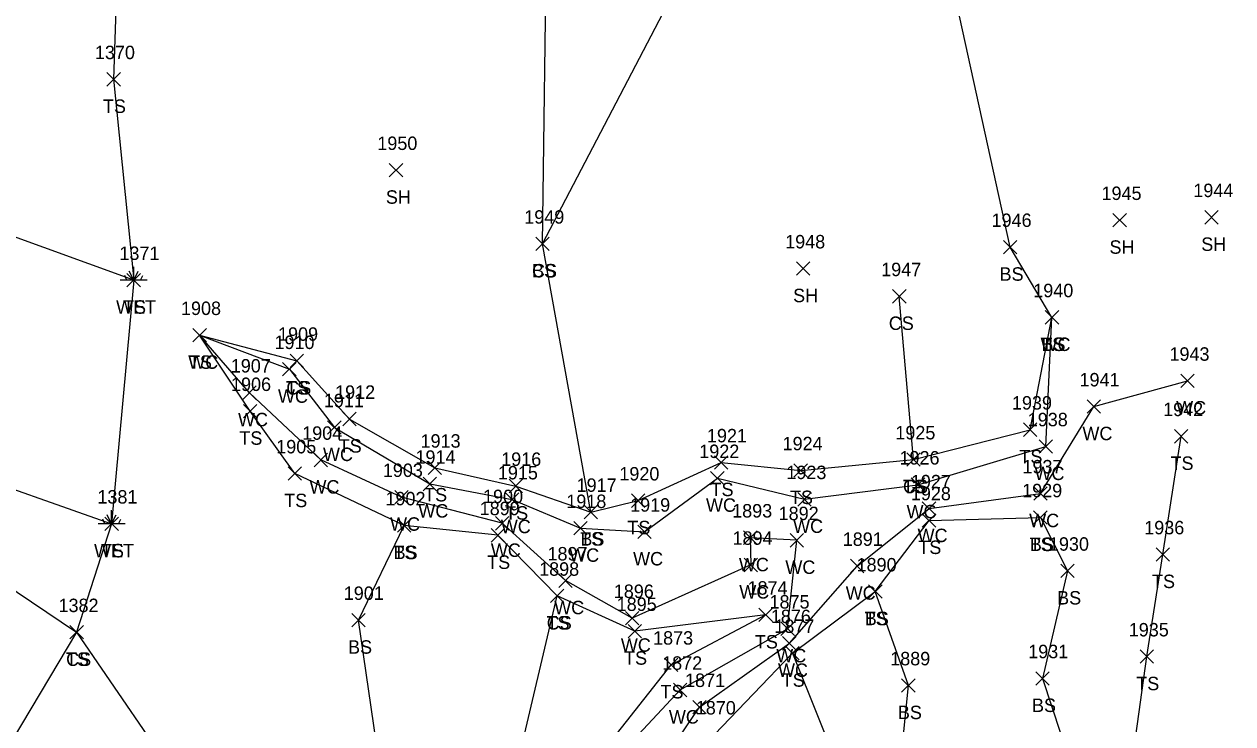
# Model space of a CAD drawing. Extents: x 1551995 to 1555700, y 777276 to 783130.
# Drawn here: x 1554974.4 to 1555154.1, y 777705.7 to 777809.8 of the extents above; entities that cross this region are included whole.
import ezdxf

# ---------------------------------------------------------------- set-up
doc = ezdxf.new("R2010")
doc.units = 0
for name, color, linetype in [('L_A', 7, 'Continuous'), ('L_I', 7, 'Continuous'), ('L_TIC', 7, 'Continuous'), ('LAWE', 7, 'Continuous'), ('LELB', 7, 'Continuous'), ('LWET', 7, 'Continuous')]:
    doc.layers.add(name, color=color, linetype=linetype)

msp = doc.modelspace()

# ---------------------------------------------------------------- linework, layer by layer
at = {"layer": 'L_TIC'}
for points in [[(1554986.68, 777800.59), (1554988.68, 777802.59)], [(1554988.68, 777800.59), (1554986.68, 777802.59)], [(1555028.67, 777787.08), (1555030.67, 777789.08)], [(1555030.67, 777787.08), (1555028.67, 777789.08)], [(1555149.91, 777780.07), (1555151.91, 777782.07)], [(1555151.91, 777780.07), (1555149.91, 777782.07)], [(1555136.26, 777779.64), (1555138.26, 777781.64)], [(1555138.26, 777779.64), (1555136.26, 777781.64)], [(1555050.45, 777776.12), (1555052.45, 777778.12)], [(1555052.45, 777776.12), (1555050.45, 777778.12)], [(1555050.45, 777776.12), (1555052.45, 777778.12)], [(1555052.45, 777776.12), (1555050.45, 777778.12)], [(1555119.97, 777775.63), (1555121.97, 777777.63)], [(1555121.97, 777775.63), (1555119.97, 777777.63)], [(1555089.22, 777772.44), (1555091.22, 777774.44)], [(1555091.22, 777772.44), (1555089.22, 777774.44)], [(1554989.67, 777770.72), (1554991.67, 777772.72)], [(1554991.67, 777770.72), (1554989.67, 777772.72)], [(1555103.5, 777768.31), (1555105.5, 777770.31)], [(1555105.5, 777768.31), (1555103.5, 777770.31)], [(1555126.2, 777765.18), (1555128.2, 777767.18)], [(1555128.2, 777765.18), (1555126.2, 777767.18)], [(1555126.2, 777765.18), (1555128.2, 777767.18)], [(1555128.2, 777765.18), (1555126.2, 777767.18)], [(1555126.2, 777765.18), (1555128.2, 777767.18)], [(1555128.2, 777765.18), (1555126.2, 777767.18)], [(1554999.47, 777762.53), (1555001.47, 777764.53)], [(1555001.47, 777762.53), (1554999.47, 777764.53)], [(1554999.47, 777762.53), (1555001.47, 777764.53)], [(1555001.47, 777762.53), (1554999.47, 777764.53)], [(1555013.91, 777758.7), (1555015.91, 777760.7)], [(1555015.91, 777758.7), (1555013.91, 777760.7)], [(1555013.91, 777758.7), (1555015.91, 777760.7)], [(1555015.91, 777758.7), (1555013.91, 777760.7)], [(1555012.81, 777757.47), (1555014.81, 777759.47)], [(1555014.81, 777757.47), (1555012.81, 777759.47)], [(1555146.36, 777755.73), (1555148.36, 777757.73)], [(1555148.36, 777755.73), (1555146.36, 777757.73)], [(1555006.87, 777753.98), (1555008.87, 777755.98)], [(1555008.87, 777753.98), (1555006.87, 777755.98)], [(1555006.97, 777751.23), (1555008.97, 777753.23)], [(1555008.97, 777751.23), (1555006.97, 777753.23)], [(1555132.42, 777751.91), (1555134.42, 777753.91)], [(1555134.42, 777751.91), (1555132.42, 777753.91)], [(1555021.74, 777750.06), (1555023.74, 777752.06)], [(1555023.74, 777750.06), (1555021.74, 777752.06)], [(1555019.5, 777748.81), (1555021.5, 777750.81)], [(1555021.5, 777748.81), (1555019.5, 777750.81)], [(1555122.95, 777748.47), (1555124.95, 777750.47)], [(1555124.95, 777748.47), (1555122.95, 777750.47)], [(1555125.29, 777745.98), (1555127.29, 777747.98)], [(1555127.29, 777745.98), (1555125.29, 777747.98)], [(1555145.42, 777747.49), (1555147.42, 777749.49)], [(1555147.42, 777747.49), (1555145.42, 777749.49)], [(1555105.61, 777744.03), (1555107.61, 777746.03)], [(1555107.61, 777744.03), (1555105.61, 777746.03)], [(1555105.61, 777744.03), (1555107.61, 777746.03)], [(1555107.61, 777744.03), (1555105.61, 777746.03)], [(1555017.5, 777743.97), (1555019.5, 777745.97)], [(1555019.5, 777743.97), (1555017.5, 777745.97)], [(1555034.44, 777742.8), (1555036.44, 777744.8)], [(1555036.44, 777742.8), (1555034.44, 777744.8)], [(1555077.03, 777743.59), (1555079.03, 777745.59)], [(1555079.03, 777743.59), (1555077.03, 777745.59)], [(1555088.84, 777742.41), (1555090.84, 777744.41)], [(1555090.84, 777742.41), (1555088.84, 777744.41)], [(1555013.64, 777741.95), (1555015.64, 777743.95)], [(1555015.64, 777741.95), (1555013.64, 777743.95)], [(1555033.69, 777740.4), (1555035.69, 777742.4)], [(1555035.69, 777740.4), (1555033.69, 777742.4)], [(1555076.45, 777741.26), (1555078.45, 777743.26)], [(1555078.45, 777741.26), (1555076.45, 777743.26)], [(1555046.49, 777740.09), (1555048.49, 777742.09)], [(1555048.49, 777740.09), (1555046.49, 777742.09)], [(1555106.28, 777740.29), (1555108.28, 777742.29)], [(1555108.28, 777740.29), (1555106.28, 777742.29)], [(1555124.5, 777738.97), (1555126.5, 777740.97)], [(1555126.5, 777738.97), (1555124.5, 777740.97)], [(1555029.49, 777738.44), (1555031.49, 777740.44)], [(1555031.49, 777738.44), (1555029.49, 777740.44)], [(1555045.95, 777738.08), (1555047.95, 777740.08)], [(1555047.95, 777738.08), (1555045.95, 777740.08)], [(1555064.66, 777737.92), (1555066.66, 777739.92)], [(1555066.66, 777737.92), (1555064.66, 777739.92)], [(1555089.41, 777738.12), (1555091.41, 777740.12)], [(1555091.41, 777738.12), (1555089.41, 777740.12)], [(1555057.64, 777736.23), (1555059.64, 777738.23)], [(1555059.64, 777736.23), (1555057.64, 777738.23)], [(1555057.64, 777736.23), (1555059.64, 777738.23)], [(1555059.64, 777736.23), (1555057.64, 777738.23)], [(1555107.92, 777736.75), (1555109.92, 777738.75)], [(1555109.92, 777736.75), (1555107.92, 777738.75)], [(1555124.47, 777735.42), (1555126.47, 777737.42)], [(1555126.47, 777735.42), (1555124.47, 777737.42)], [(1555124.47, 777735.42), (1555126.47, 777737.42)], [(1555126.47, 777735.42), (1555124.47, 777737.42)], [(1554986.39, 777734.48), (1554988.39, 777736.48)], [(1554988.39, 777734.48), (1554986.39, 777736.48)], [(1555029.87, 777734.22), (1555031.87, 777736.22)], [(1555031.87, 777734.22), (1555029.87, 777736.22)], [(1555029.87, 777734.22), (1555031.87, 777736.22)], [(1555031.87, 777734.22), (1555029.87, 777736.22)], [(1555044.46, 777734.55), (1555046.46, 777736.55)], [(1555046.46, 777734.55), (1555044.46, 777736.55)], [(1555056.11, 777733.82), (1555058.11, 777735.82)], [(1555058.11, 777733.82), (1555056.11, 777735.82)], [(1555065.61, 777733.28), (1555067.61, 777735.28)], [(1555067.61, 777733.28), (1555065.61, 777735.28)], [(1555107.92, 777734.98), (1555109.92, 777736.98)], [(1555109.92, 777734.98), (1555107.92, 777736.98)], [(1555043.81, 777732.76), (1555045.81, 777734.76)], [(1555045.81, 777732.76), (1555043.81, 777734.76)], [(1555081.35, 777732.41), (1555083.35, 777734.41)], [(1555083.35, 777732.41), (1555081.35, 777734.41)], [(1555088.26, 777732.02), (1555090.26, 777734.02)], [(1555090.26, 777732.02), (1555088.26, 777734.02)], [(1555142.67, 777729.91), (1555144.67, 777731.91)], [(1555144.67, 777729.91), (1555142.67, 777731.91)], [(1555081.41, 777728.35), (1555083.41, 777730.35)], [(1555083.41, 777728.35), (1555081.41, 777730.35)], [(1555097.22, 777728.19), (1555099.22, 777730.19)], [(1555099.22, 777728.19), (1555097.22, 777730.19)], [(1555128.52, 777727.47), (1555130.52, 777729.47)], [(1555130.52, 777727.47), (1555128.52, 777729.47)], [(1555053.88, 777726.02), (1555055.88, 777728.02)], [(1555055.88, 777726.02), (1555053.88, 777728.02)], [(1555099.93, 777724.39), (1555101.93, 777726.39)], [(1555101.93, 777724.39), (1555099.93, 777726.39)], [(1555099.93, 777724.39), (1555101.93, 777726.39)], [(1555101.93, 777724.39), (1555099.93, 777726.39)], [(1555052.64, 777723.75), (1555054.64, 777725.75)], [(1555054.64, 777723.75), (1555052.64, 777725.75)], [(1555052.64, 777723.75), (1555054.64, 777725.75)], [(1555054.64, 777723.75), (1555052.64, 777725.75)], [(1555083.63, 777720.93), (1555085.63, 777722.93)], [(1555085.63, 777720.93), (1555083.63, 777722.93)], [(1555023.1, 777720.15), (1555025.1, 777722.15)], [(1555025.1, 777720.15), (1555023.1, 777722.15)], [(1555063.79, 777720.44), (1555065.79, 777722.44)], [(1555065.79, 777720.44), (1555063.79, 777722.44)], [(1555086.9, 777718.87), (1555088.9, 777720.87)], [(1555088.9, 777718.87), (1555086.9, 777720.87)], [(1554981.18, 777718.34), (1554983.18, 777720.34)], [(1554983.18, 777718.34), (1554981.18, 777720.34)], [(1554981.18, 777718.34), (1554983.18, 777720.34)], [(1554983.18, 777718.34), (1554981.18, 777720.34)], [(1555064.17, 777718.51), (1555066.17, 777720.51)], [(1555066.17, 777718.51), (1555064.17, 777720.51)], [(1555087.15, 777716.7), (1555089.15, 777718.7)], [(1555089.15, 777716.7), (1555087.15, 777718.7)], [(1555087.61, 777715.24), (1555089.61, 777717.24)], [(1555089.61, 777715.24), (1555087.61, 777717.24)], [(1555087.61, 777715.24), (1555089.61, 777717.24)], [(1555089.61, 777715.24), (1555087.61, 777717.24)], [(1555069.58, 777713.5), (1555071.58, 777715.5)], [(1555071.58, 777713.5), (1555069.58, 777715.5)], [(1555140.32, 777714.72), (1555142.32, 777716.72)], [(1555142.32, 777714.72), (1555140.32, 777716.72)], [(1555104.85, 777710.42), (1555106.85, 777712.42)], [(1555106.85, 777710.42), (1555104.85, 777712.42)], [(1555124.79, 777711.48), (1555126.79, 777713.48)], [(1555126.79, 777711.48), (1555124.79, 777713.48)], [(1555070.93, 777709.76), (1555072.93, 777711.76)], [(1555072.93, 777709.76), (1555070.93, 777711.76)], [(1555073.78, 777707.2), (1555075.78, 777709.2)], [(1555075.78, 777707.2), (1555073.78, 777709.2)]]:
    msp.add_lwpolyline(points, dxfattribs=at)
at = {"layer": 'LAWE'}
for points in [[(1555058.18, 777696.03), (1555071.93, 777710.76), (1555087.9, 777719.87), (1555089.26, 777733.02), (1555082.35, 777733.41), (1555082.41, 777729.35), (1555064.79, 777721.44), (1555054.88, 777727.02), (1555045.46, 777735.55), (1555030.49, 777739.44), (1555018.5, 777744.97), (1555007.87, 777754.98), (1555000.47, 777763.53), (1555013.81, 777758.47), (1555020.5, 777749.81), (1555034.69, 777741.4), (1555046.95, 777739.08), (1555057.11, 777734.82), (1555066.61, 777734.28), (1555077.45, 777742.26), (1555090.41, 777739.12), (1555107.28, 777741.29), (1555126.29, 777746.98), (1555127.2, 777766.18)], [(1554896.13, 777669.49), (1554914.18, 777672.74), (1554933.67, 777664.23), (1554957.57, 777659.67), (1554982.43, 777660.34), (1555001.98, 777663.11), (1555028.12, 777669.98), (1555046.42, 777677.46), (1555063.93, 777692.17), (1555074.78, 777708.2), (1555088.15, 777717.7), (1555098.22, 777729.19), (1555108.92, 777737.75), (1555125.5, 777739.97), (1555133.42, 777752.91), (1555147.36, 777756.73)]]:
    msp.add_lwpolyline(points, dxfattribs=at)
at = {"layer": 'LELB'}
for points in [[(1555000.87, 778001.08), (1555009.49, 778000.82), (1555019.32, 777999.5), (1555016.45, 777976.79), (1555007.25, 777941.96), (1555001.69, 777908.63), (1554997.48, 777871.9), (1554988.59, 777829.9), (1554987.68, 777801.59), (1554990.67, 777771.72), (1554987.39, 777735.48), (1554982.18, 777719.34), (1554965.91, 777692.12), (1554960.8, 777672.01)], [(1555058.64, 777737.23), (1555051.45, 777777.12), (1555052.07, 777825.35), (1555065.17, 777859.34), (1555070.04, 777906.27), (1555056.77, 777940.6), (1555061.21, 777980.52)], [(1555051.45, 777777.12), (1555078, 777828.03), (1555081.51, 777855.89), (1555080.79, 777900.32), (1555083.18, 777937.78), (1555094.59, 777961.85)], [(1555127.2, 777766.18), (1555120.97, 777776.63), (1555109.74, 777827.97), (1555106.34, 777846.22), (1555120.85, 777888.04), (1555124.28, 777930.52)], [(1555106.61, 777745.03), (1555104.5, 777769.31)], [(1555056.56, 777696.7), (1555070.58, 777714.5), (1555084.63, 777721.93), (1555065.17, 777719.51), (1555053.64, 777724.75), (1555044.81, 777733.76), (1555030.87, 777735.22), (1555014.64, 777742.95), (1555007.97, 777752.23), (1555000.47, 777763.53), (1555014.91, 777759.7), (1555022.74, 777751.06), (1555035.44, 777743.8), (1555047.49, 777741.09), (1555058.64, 777737.23), (1555065.66, 777738.92), (1555078.03, 777744.59), (1555089.84, 777743.41), (1555106.61, 777745.03), (1555123.95, 777749.47), (1555127.2, 777766.18)], [(1555140.03, 777674.45), (1555138.72, 777697.14), (1555141.32, 777715.72), (1555143.67, 777730.91), (1555146.42, 777748.49)], [(1554938.36, 777737.56), (1554957.8, 777735.77), (1554982.18, 777719.34), (1554998.86, 777694.95), (1555004.18, 777677.14)], [(1555030.13, 777679.61), (1555024.1, 777721.15), (1555030.87, 777735.22)], [(1555031.47, 777662.83), (1555047.6, 777675.77), (1555065.89, 777691.82), (1555077.02, 777704.11), (1555088.61, 777716.24), (1555100.93, 777725.39), (1555108.92, 777735.98), (1555125.47, 777736.42)], [(1555125.47, 777736.42), (1555129.52, 777728.47), (1555125.79, 777712.48), (1555131.21, 777696.07), (1555140.03, 777674.45)], [(1555043.88, 777683.29), (1555053.64, 777724.75)], [(1555118.46, 777622.99), (1555121.93, 777635.07), (1555124.19, 777660.72), (1555119.98, 777681.1), (1555104.78, 777700.68), (1555105.85, 777711.42), (1555100.93, 777725.39)], [(1555088.61, 777716.24), (1555096.46, 777696.69), (1555101.68, 777679.67), (1555104.15, 777652.17), (1555118.46, 777622.99), (1555114.53, 777595.03), (1555107.52, 777571.18), (1555085.84, 777534.97)]]:
    msp.add_lwpolyline(points, dxfattribs=at)
at = {"layer": 'LWET'}
for p, q in [((1554990.67, 777771.72), (1554990, 777773.06)), ((1554990.67, 777771.72), (1554990.67, 777773.72)), ((1554990.67, 777771.72), (1554991.33, 777773.06)), ((1554992.67, 777771.72), (1554988.67, 777771.72)), ((1554989.67, 777771.72), (1554989.33, 777772.39)), ((1554991.67, 777771.72), (1554992, 777772.39)), ((1554987.39, 777735.48), (1554987.39, 777737.48)), ((1554989.39, 777735.48), (1554985.39, 777735.48)), ((1554986.39, 777735.48), (1554986.06, 777736.15)), ((1554987.39, 777735.48), (1554986.73, 777736.82)), ((1554987.39, 777735.48), (1554988.06, 777736.82)), ((1554988.39, 777735.48), (1554988.73, 777736.15))]:
    msp.add_line(p, q, dxfattribs=at)
msp.add_lwpolyline([(1554990.67, 777771.72), (1554970.57, 777779), (1554953.35, 777779.92), (1554929.46, 777763.36), (1554920.45, 777745.2), (1554938.36, 777737.56), (1554963.47, 777743.88), (1554987.39, 777735.48)], dxfattribs=at)

# ---------------------------------------------------------------- texts
at = {"layer": 'L_A'}
for s, p in [('TS', (1554986.09, 777796.59)), ('SH', (1555028.16, 777783.08)), ('SH', (1555135.75, 777775.64)), ('SH', (1555149.4, 777776.07)), ('CS', (1555049.89, 777772.12)), ('BS', (1555049.89, 777772.12)), ('BS', (1555119.41, 777771.63)), ('SH', (1555088.71, 777768.44)), ('WET', (1554988.05, 777766.72)), ('TS', (1554989.08, 777766.72)), ('CS', (1555102.94, 777764.31)), ('WC', (1555125.5, 777761.18)), ('TS', (1555125.61, 777761.18)), ('BS', (1555125.64, 777761.18)), ('WC', (1554998.77, 777758.53)), ('TS', (1554998.88, 777758.53)), ('WC', (1555012.12, 777753.47)), ('TS', (1555013.32, 777754.7)), ('CS', (1555013.35, 777754.7)), ('WC', (1555145.67, 777751.73)), ('WC', (1555006.18, 777749.98)), ('WC', (1555131.73, 777747.91)), ('TS', (1555006.38, 777747.23)), ('TS', (1555021.15, 777746.06)), ('WC', (1555018.81, 777744.81)), ('TS', (1555122.36, 777744.47)), ('TS', (1555144.83, 777743.49)), ('WC', (1555124.6, 777741.98)), ('WC', (1555016.8, 777739.97)), ('TS', (1555033.85, 777738.8)), ('TS', (1555076.44, 777739.59)), ('TS', (1555105.02, 777740.03)), ('CS', (1555105.05, 777740.03)), ('TS', (1555013.05, 777737.95)), ('WC', (1555075.76, 777737.26)), ('TS', (1555088.25, 777738.41)), ('WC', (1555032.99, 777736.4)), ('TS', (1555045.9, 777736.09)), ('WC', (1555105.58, 777736.29)), ('WC', (1555028.79, 777734.44)), ('WC', (1555045.25, 777734.08)), ('TS', (1555064.07, 777733.92)), ('WC', (1555088.71, 777734.12)), ('WC', (1555123.81, 777734.97)), ('TS', (1555057.05, 777732.23)), ('BS', (1555057.08, 777732.23)), ('WC', (1555107.22, 777732.75)), ('TS', (1555123.88, 777731.42)), ('BS', (1555123.91, 777731.42)), ('WET', (1554984.77, 777730.48)), ('TS', (1554985.8, 777730.48)), ('TS', (1555029.28, 777730.22)), ('BS', (1555029.31, 777730.22)), ('WC', (1555043.77, 777730.55)), ('WC', (1555055.42, 777729.82)), ('TS', (1555107.33, 777730.98)), ('TS', (1555043.22, 777728.76)), ('WC', (1555064.92, 777729.28)), ('WC', (1555080.65, 777728.41)), ('WC', (1555087.56, 777728.02)), ('WC', (1555080.71, 777724.35)), ('TS', (1555142.08, 777725.91)), ('WC', (1555096.53, 777724.19)), ('BS', (1555127.97, 777723.47)), ('WC', (1555053.19, 777722.02)), ('TS', (1555052.05, 777719.75)), ('CS', (1555052.08, 777719.75)), ('TS', (1555099.34, 777720.39)), ('BS', (1555099.37, 777720.39)), ('BS', (1555022.54, 777716.15)), ('WC', (1555063.1, 777716.44)), ('TS', (1555083.03, 777716.93)), ('TS', (1554980.59, 777714.34)), ('CS', (1554980.62, 777714.34)), ('TS', (1555063.58, 777714.51)), ('WC', (1555086.21, 777714.87)), ('WC', (1555086.46, 777712.7)), ('TS', (1555087.02, 777711.24)), ('TS', (1555087.02, 777711.24)), ('TS', (1555139.73, 777710.72)), ('TS', (1555068.99, 777709.5)), ('BS', (1555104.29, 777706.42)), ('BS', (1555124.23, 777707.48)), ('WC', (1555070.24, 777705.76))]:
    msp.add_text(s, height=2, dxfattribs=at).set_placement(p)
at = {"layer": 'L_I'}
for s, p in [('1370', (1554984.9, 777804.59)), ('1950', (1555026.89, 777791.08)), ('1945', (1555134.57, 777783.64)), ('1944', (1555148.22, 777784.07)), ('1949', (1555048.74, 777780.12)), ('1949', (1555048.74, 777780.12)), ('1946', (1555118.22, 777779.63)), ('1948', (1555087.53, 777776.44)), ('1371', (1554988.54, 777774.72)), ('1371', (1554988.54, 777774.72)), ('1947', (1555101.81, 777772.31)), ('1940', (1555124.42, 777769.18)), ('1940', (1555124.42, 777769.18)), ('1940', (1555124.42, 777769.18)), ('1908', (1554997.7, 777766.53)), ('1908', (1554997.7, 777766.53)), ('1909', (1555012.13, 777762.7)), ('1909', (1555012.13, 777762.7)), ('1910', (1555011.6, 777761.47)), ('1943', (1555144.67, 777759.73)), ('1907', (1555005.1, 777757.98)), ('1906', (1555005.14, 777755.23)), ('1941', (1555131.3, 777755.91)), ('1912', (1555020.61, 777754.06)), ('1911', (1555018.94, 777752.81)), ('1939', (1555121.25, 777752.47)), ('1942', (1555143.73, 777751.49)), ('1938', (1555123.6, 777749.98)), ('1904', (1555015.72, 777747.97)), ('1921', (1555075.9, 777747.59)), ('1925', (1555103.91, 777748.03)), ('1925', (1555103.91, 777748.03)), ('1905', (1555011.86, 777745.95)), ('1913', (1555033.32, 777746.8)), ('1924', (1555087.15, 777746.41)), ('1914', (1555032.56, 777744.4)), ('1916', (1555045.31, 777744.09)), ('1922', (1555074.76, 777745.26)), ('1926', (1555104.53, 777744.29)), ('1903', (1555027.71, 777742.44)), ('1937', (1555122.81, 777742.97)), ('1915', (1555044.82, 777742.08)), ('1920', (1555062.88, 777741.92)), ('1923', (1555087.71, 777742.12)), ('1927', (1555106.22, 777740.75)), ('1917', (1555056.52, 777740.23)), ('1917', (1555056.52, 777740.23)), ('1928', (1555106.22, 777738.98)), ('1929', (1555122.77, 777739.42)), ('1929', (1555122.77, 777739.42)), ('1381', (1554985.27, 777738.48)), ('1381', (1554985.27, 777738.48)), ('1902', (1555028.1, 777738.22)), ('1902', (1555028.1, 777738.22)), ('1900', (1555042.61, 777738.55)), ('1918', (1555054.99, 777737.82)), ('1919', (1555064.48, 777737.28)), ('1899', (1555042.11, 777736.76)), ('1893', (1555079.65, 777736.41)), ('1892', (1555086.56, 777736.02)), ('1936', (1555140.92, 777733.91)), ('1894', (1555079.71, 777732.35)), ('1891', (1555096.09, 777732.19)), ('1930', (1555126.75, 777731.47)), ('1897', (1555052.19, 777730.02)), ('1890', (1555098.15, 777728.39)), ('1890', (1555098.15, 777728.39)), ('1898', (1555050.95, 777727.75)), ('1898', (1555050.95, 777727.75)), ('1896', (1555062.05, 777724.44)), ('1874', (1555081.93, 777724.93)), ('1901', (1555021.9, 777724.15)), ('1895', (1555062.48, 777722.51)), ('1875', (1555085.21, 777722.87)), ('1382', (1554979.49, 777722.34)), ('1382', (1554979.49, 777722.34)), ('1876', (1555085.4, 777720.7)), ('1877', (1555085.92, 777719.24)), ('1877', (1555085.92, 777719.24)), ('1873', (1555067.89, 777717.5)), ('1935', (1555138.62, 777718.72)), ('1931', (1555123.67, 777715.48)), ('1872', (1555069.24, 777713.76)), ('1889', (1555103.15, 777714.42)), ('1871', (1555072.65, 777711.2)), ('1870', (1555074.24, 777707.11)), ('1870', (1555074.24, 777707.11))]:
    msp.add_text(s, height=2, dxfattribs=at).set_placement(p)

doc.saveas('drawing.dxf')
